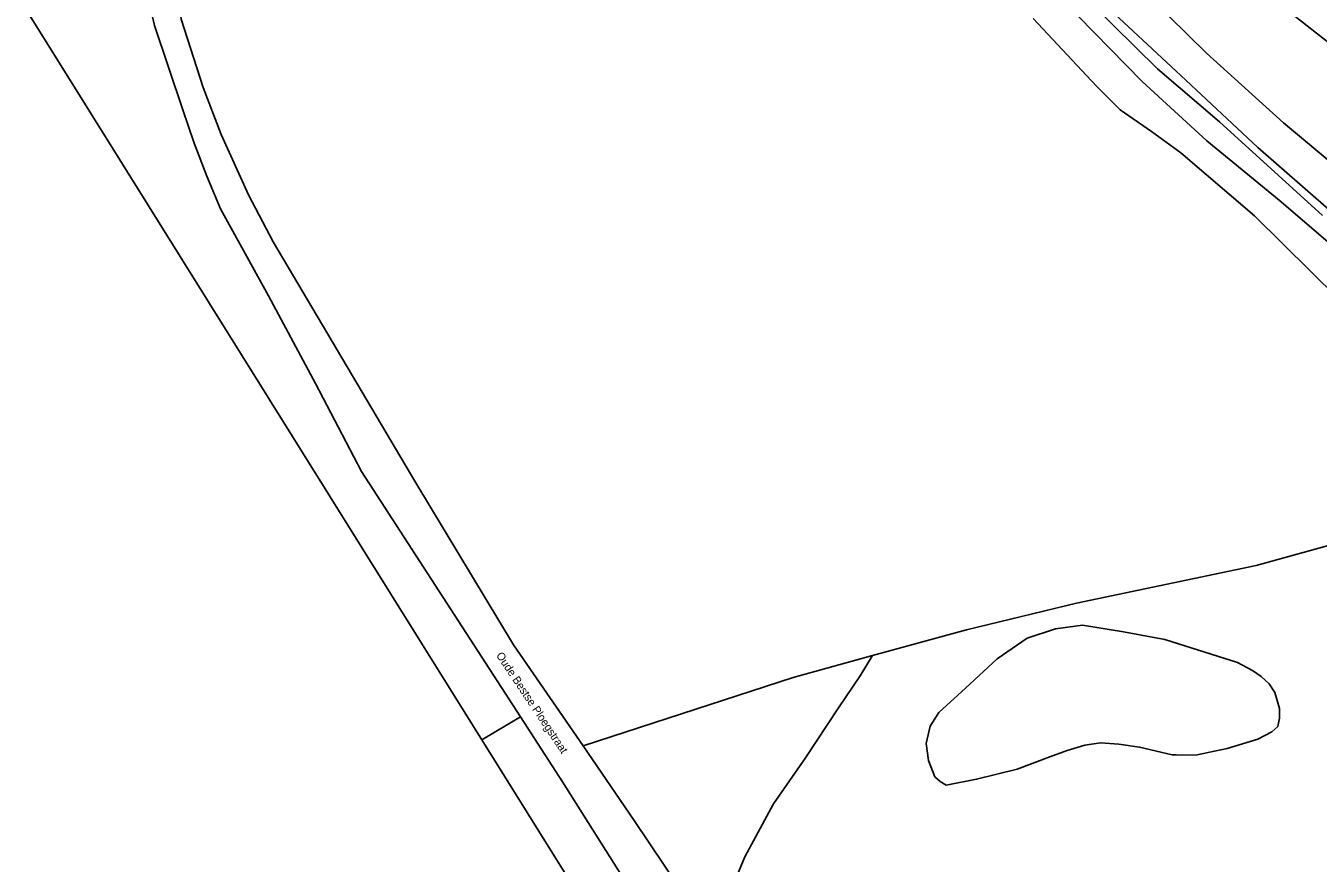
# Model space of a CAD drawing. Extents: x 155209 to 156748, y 385356 to 388487.
# Drawn here: x 155595.8 to 155757.3, y 388094.7 to 388199.3 of the extents above; entities that cross this region are included whole.
import ezdxf

# ---------------------------------------------------------------- set-up
doc = ezdxf.new("R2010")
doc.units = 0
for name, color, linetype in [('IMGEO_Berm_groen', 7, 'Continuous'), ('IMGEO_Gemengd_bos', 7, 'Continuous'), ('IMGEO_Grasland_overig', 7, 'Continuous'), ('IMGEO_Groenvoorziening', 7, 'Continuous'), ('IMGEO_Loofbos', 7, 'Continuous'), ('IMGEO_Oever', 7, 'Continuous'), ('IMGEO_Openbare_ruimte_label', 7, 'Continuous'), ('IMGEO_Rijbaan_lokaal_onverhard', 7, 'Continuous'), ('IMGEO_Waterloop', 7, 'Continuous')]:
    doc.layers.add(name, color=color, linetype=linetype)

msp = doc.modelspace()

# ---------------------------------------------------------------- linework, layer by layer
at = {"layer": 'IMGEO_Berm_groen'}
msp.add_lwpolyline([(155754.37, 388200.55), (155764.43, 388192.66)], dxfattribs=at)
msp.add_lwpolyline([(155662.86, 388104.9), (155657.6, 388113.02), (155652.78, 388110.13), (155675.45, 388073.8), (155677.13, 388071.1), (155684.5, 388059.3), (155701.96, 388031.36), (155703.79, 388028.45), (155721.57, 388000), (155728.33, 387989.18), (155730.76, 387991.02), (155730.6, 387993.71), (155730.06, 387997.21), (155729.14, 387999.02), (155728.84, 387999.68), (155723.8, 388008.82), (155717.82, 388017.7), (155711.7, 388026.49), (155687.52, 388065.84)], close=True, dxfattribs=at)
at = {"layer": 'IMGEO_Gemengd_bos'}
msp.add_lwpolyline([(155588.06, 388213.76), (155596.12, 388200.89), (155652.78, 388110.13), (155657.6, 388113.02), (155637.74, 388143.66), (155631.98, 388154.66), (155626.1, 388165.59), (155620.11, 388176.47), (155618.41, 388180.55), (155616.84, 388184.68), (155615.39, 388188.86), (155611.86, 388199.39), (155610.91, 388203.55), (155609.64, 388210.6), (155608.15, 388224.05), (155607.37, 388231.84), (155606.57, 388237.08), (155605.13, 388243.9), (155602.51, 388249.67), (155599.37, 388257.03), (155595.54, 388263.13)], dxfattribs=at)
at = {"layer": 'IMGEO_Grasland_overig'}
for points in [[(155596.12, 388200.89), (155588.06, 388213.76), (155572.44, 388238.02), (155571.95, 388238.92), (155561.42, 388232.39), (155554.81, 388228.21), (155553.63, 388227.5), (155543.45, 388221.41), (155510.54, 388201.02), (155477.58, 388180.3), (155442.48, 388158.1), (155418.26, 388143.55), (155406.55, 388136.59), (155413.68, 388125.71), (155425.01, 388108.6), (155432.18, 388097.76), (155489.63, 388002.06), (155489.82, 388001.75), (155506.78, 387974.73), (155510.1, 387968.93), (155675.45, 388073.8), (155652.78, 388110.13)], [(155751.89, 388116.04), (155752.45, 388114.05), (155752.46, 388112.84), (155752.25, 388111.82), (155751.49, 388111.15), (155749.74, 388110.23), (155745.91, 388109.06), (155741.95, 388108.24), (155739.57, 388108.26), (155739.05, 388108.27), (155734.98, 388109.23), (155732.38, 388109.6), (155730.08, 388109.75), (155728.14, 388109.45), (155725.94, 388108.8), (155723.77, 388108.02), (155719.7, 388106.48), (155714.61, 388105.22), (155710.79, 388104.49), (155710.05, 388104.91), (155709.38, 388105.52), (155708.6, 388107.57), (155708.3, 388109.66), (155708.79, 388111.85), (155709.87, 388113.56), (155713.24, 388116.57), (155717.17, 388120.25), (155720.91, 388122.84), (155724.49, 388123.99), (155727.86, 388124.45), (155732.97, 388123.61), (155738.14, 388122.67), (155747.21, 388119.8), (155749.07, 388118.78), (155750.17, 388118.04), (155751.18, 388117.13)]]:
    msp.add_lwpolyline(points, close=True, dxfattribs=at)
for points in [[(155736.27, 388202.93), (155743.34, 388195.94), (155752.98, 388187.23), (155766.78, 388175.68)], [(155766.78, 388175.68), (155752.98, 388187.23), (155743.34, 388195.94), (155736.27, 388202.93)], [(155730.63, 388201.97), (155740.12, 388193.12), (155749.77, 388184.12), (155761.58, 388173.79)], [(155764.43, 388192.66), (155754.37, 388200.55)], [(155767.45, 388136.88), (155749.53, 388131.93), (155727.1, 388127.23), (155713.34, 388123.89), (155701.62, 388120.67), (155700.06, 388118.12), (155697.34, 388114.12), (155693.22, 388107.88), (155689.22, 388102.12), (155685.64, 388095.5), (155681.5, 388085.61)]]:
    msp.add_lwpolyline(points, dxfattribs=at)
at = {"layer": 'IMGEO_Groenvoorziening'}
msp.add_lwpolyline([(155681.5, 388085.61), (155685.64, 388095.5), (155689.22, 388102.12), (155693.22, 388107.88), (155697.34, 388114.12), (155700.06, 388118.12), (155701.62, 388120.67), (155691.67, 388117.94), (155665.43, 388109.37), (155671.83, 388100.07)], close=True, dxfattribs=at)
at = {"layer": 'IMGEO_Loofbos'}
for points in [[(155595.09, 388269.66), (155601.27, 388260.24), (155604.34, 388254.6), (155607.96, 388245.53), (155609.7, 388238.7), (155611.06, 388232.58), (155611.98, 388224.59), (155613.12, 388217.41), (155613.98, 388211.12), (155615.18, 388200.17), (155617.95, 388191.62), (155620.19, 388185.75), (155623.63, 388178.23), (155626.7, 388172.34), (155644.54, 388142.26), (155656.75, 388121.99), (155665.43, 388109.37), (155691.67, 388117.94), (155701.62, 388120.67), (155713.34, 388123.89), (155727.1, 388127.23), (155749.53, 388131.93), (155767.45, 388136.88)], [(155759.83, 388165.25), (155749.36, 388175.58), (155740.13, 388183.48), (155736.46, 388186.14), (155732.55, 388188.83), (155729.58, 388191.81), (155721.66, 388200.27)]]:
    msp.add_lwpolyline(points, dxfattribs=at)
msp.add_lwpolyline([(155749.07, 388118.78), (155747.21, 388119.8), (155738.14, 388122.67), (155732.97, 388123.61), (155727.86, 388124.45), (155724.49, 388123.99), (155720.91, 388122.84), (155717.17, 388120.25), (155713.24, 388116.57), (155709.87, 388113.56), (155708.79, 388111.85), (155708.3, 388109.66), (155708.6, 388107.57), (155709.38, 388105.52), (155710.05, 388104.91), (155710.79, 388104.49), (155714.61, 388105.22), (155719.7, 388106.48), (155723.77, 388108.02), (155725.94, 388108.8), (155728.14, 388109.45), (155730.08, 388109.75), (155732.38, 388109.6), (155734.98, 388109.23), (155739.05, 388108.27), (155739.57, 388108.26), (155741.95, 388108.24), (155745.91, 388109.06), (155749.74, 388110.23), (155751.49, 388111.15), (155752.25, 388111.82), (155752.46, 388112.84), (155752.45, 388114.05), (155751.89, 388116.04), (155751.18, 388117.13), (155750.17, 388118.04)], close=True, dxfattribs=at)
at = {"layer": 'IMGEO_Oever'}
for points in [[(155701.02, 388229.66), (155737.23, 388193.98), (155744.98, 388187.35), (155757.85, 388175.63)], [(155761.18, 388170.06), (155752.66, 388177.35), (155743.39, 388184.96), (155735.29, 388192.37), (155727.32, 388200.53)], [(155761.58, 388173.79), (155749.77, 388184.12), (155740.12, 388193.12), (155730.63, 388201.97)], [(155721.66, 388200.27), (155729.58, 388191.81), (155732.55, 388188.83), (155736.46, 388186.14), (155740.13, 388183.48), (155749.36, 388175.58), (155759.83, 388165.25)]]:
    msp.add_lwpolyline(points, dxfattribs=at)
at = {"layer": 'IMGEO_Rijbaan_lokaal_onverhard'}
for points in [[(155681.5, 388085.61), (155671.83, 388100.07), (155665.43, 388109.37), (155656.75, 388121.99), (155644.54, 388142.26), (155626.7, 388172.34), (155623.63, 388178.23), (155620.19, 388185.75), (155617.95, 388191.62), (155615.18, 388200.17), (155613.98, 388211.12), (155613.12, 388217.41), (155611.98, 388224.59), (155611.06, 388232.58), (155609.7, 388238.7), (155607.96, 388245.53), (155604.34, 388254.6), (155601.27, 388260.24), (155595.09, 388269.66)], [(155595.54, 388263.13), (155599.37, 388257.03), (155602.51, 388249.67), (155605.13, 388243.9), (155606.57, 388237.08), (155607.37, 388231.84), (155608.15, 388224.05), (155609.64, 388210.6), (155610.91, 388203.55), (155611.86, 388199.39), (155615.39, 388188.86), (155616.84, 388184.68), (155618.41, 388180.55), (155620.11, 388176.47), (155626.1, 388165.59), (155631.98, 388154.66), (155637.74, 388143.66), (155657.6, 388113.02), (155662.86, 388104.9), (155687.52, 388065.84)]]:
    msp.add_lwpolyline(points, dxfattribs=at)
at = {"layer": 'IMGEO_Waterloop'}
msp.add_lwpolyline([(155757.85, 388175.63), (155744.98, 388187.35), (155737.23, 388193.98), (155701.02, 388229.66), (155650.36, 388279.17), (155648.89, 388277.43), (155654.37, 388272.52), (155663.17, 388264.4), (155669.7, 388258.1), (155678.32, 388249.78), (155687.33, 388240.69), (155710.56, 388216.98), (155719.6, 388207.96), (155727.32, 388200.53), (155735.29, 388192.37), (155743.39, 388184.96), (155752.66, 388177.35), (155761.18, 388170.06)], dxfattribs=at)

# ---------------------------------------------------------------- texts
at = {"layer": 'IMGEO_Openbare_ruimte_label'}
msp.add_text('Oude Bestse Ploegstraat', height=1, rotation=303.706, dxfattribs=at).set_placement((155654.52, 388120.69))

doc.saveas('drawing.dxf')
